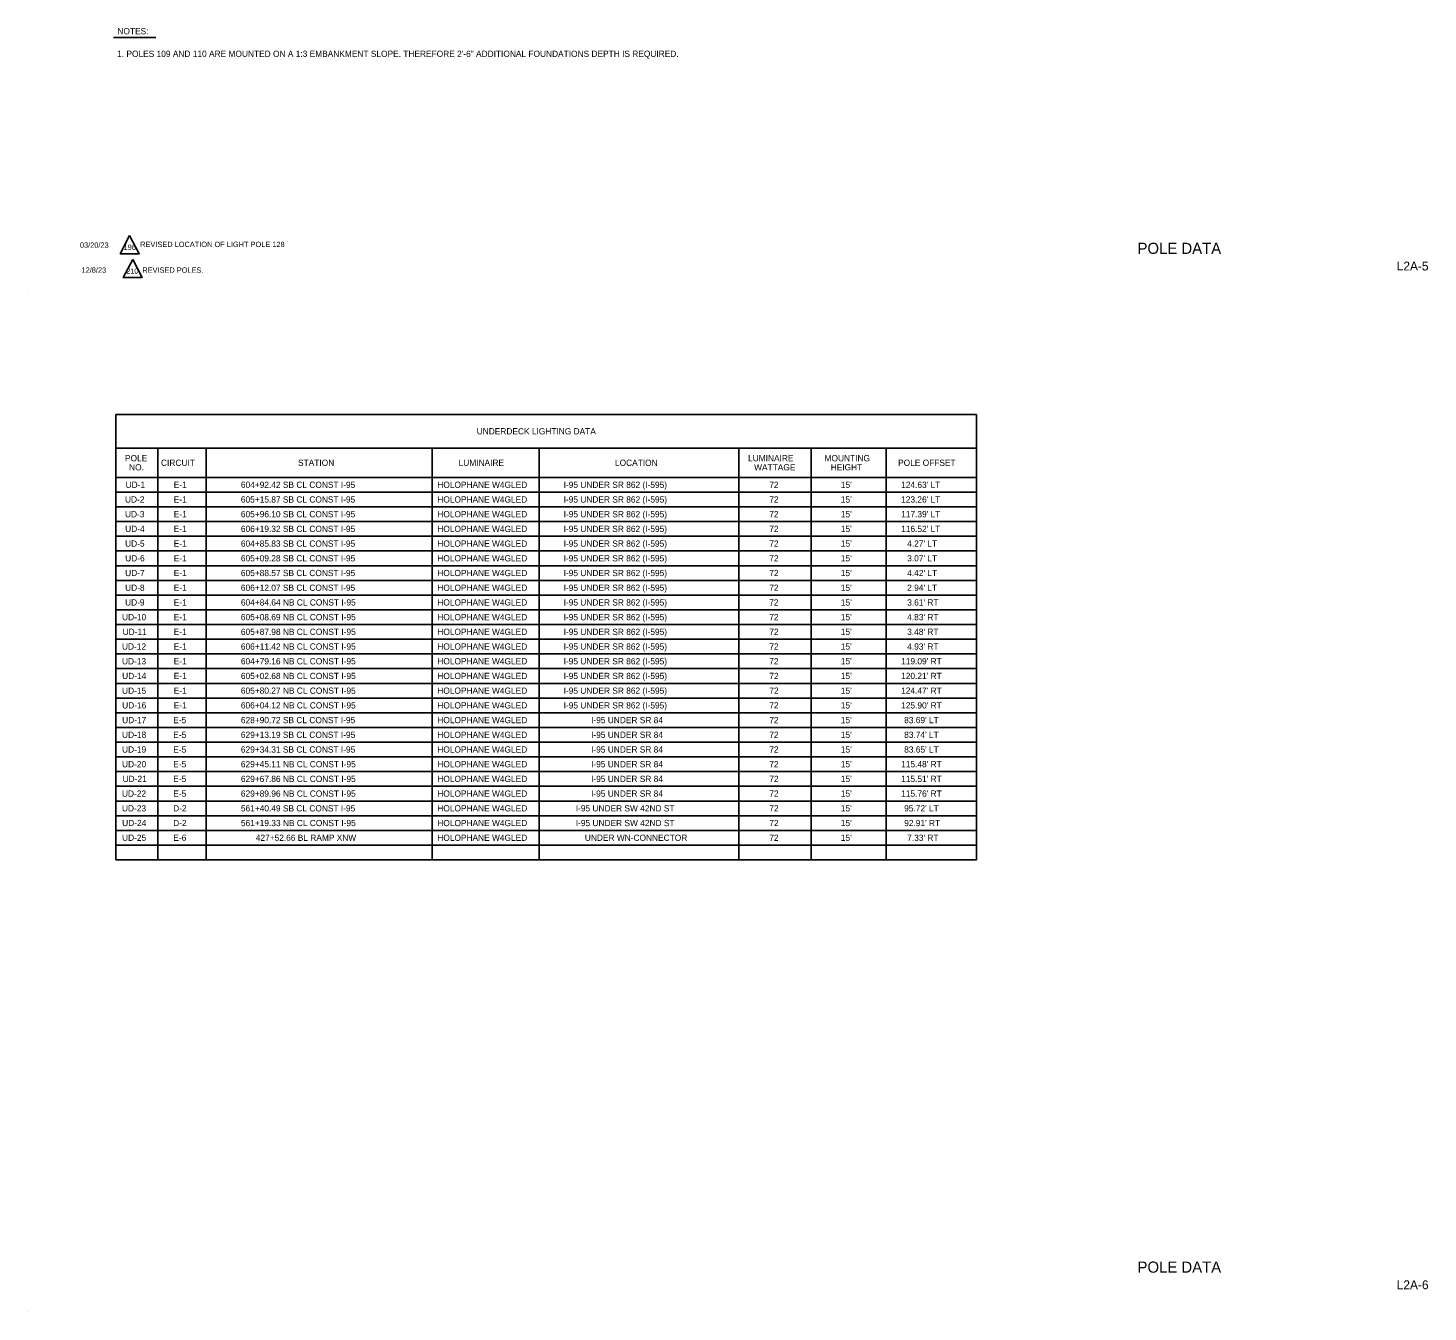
# Model space of a CAD drawing. Extents: x -818.1 to -802.4, y -2221.2 to -2187.7.
# Drawn here: x -818.09 to -802.38, y -2221.15 to -2206.75 of the extents above; entities that cross this region are included whole.
import ezdxf

# ---------------------------------------------------------------- set-up
doc = ezdxf.new("R2010")
doc.units = 0
for name, color, linetype in [('AdhocPoint_dp', 7, 'Continuous'), ('Cloud_dp', 7, 'Continuous'), ('SumBoxBorder_dp', 7, 'Continuous'), ('SumBoxLines_dp', 7, 'Continuous'), ('SumBoxLinesMin_dp', 7, 'Continuous'), ('TextLabel', 7, 'Continuous'), ('TextMisc', 7, 'Continuous'), ('TextShtNo', 7, 'Continuous')]:
    doc.layers.add(name, color=color, linetype=linetype)

msp = doc.modelspace()

# ---------------------------------------------------------------- linework, layer by layer
at = {"layer": 'AdhocPoint_dp'}
for p, q in [((-818.086, -2209.723), (-818.086, -2209.723)), ((-818.086, -2221.153), (-818.086, -2221.153))]:
    msp.add_line(p, q, dxfattribs=at)
at = {"layer": 'Cloud_dp'}
for points in [[(-816.946, -2209.076), (-817.052, -2209.281), (-816.839, -2209.281)], [(-816.911, -2209.344), (-817.017, -2209.547), (-816.806, -2209.547)]]:
    msp.add_lwpolyline(points, close=True, dxfattribs=at)
at = {"layer": 'SumBoxBorder_dp'}
for p, q in [((-817.101, -2211.085), (-807.448, -2211.085)), ((-817.101, -2211.085), (-817.101, -2216.08)), ((-807.448, -2216.08), (-807.448, -2211.085)), ((-817.101, -2211.46), (-807.448, -2211.46)), ((-817.101, -2211.46), (-807.448, -2211.46)), ((-807.448, -2211.79), (-807.448, -2211.955)), ((-807.448, -2212.285), (-807.448, -2212.615)), ((-807.448, -2213.11), (-807.448, -2213.605)), ((-807.448, -2214.43), (-807.448, -2214.595)), ((-807.448, -2215.255), (-807.448, -2215.42)), ((-807.448, -2215.915), (-807.448, -2216.08)), ((-817.101, -2216.08), (-809.301, -2216.08)), ((-809.301, -2216.08), (-808.461, -2216.08)), ((-808.461, -2216.08), (-807.448, -2216.08))]:
    msp.add_line(p, q, dxfattribs=at)
at = {"layer": 'SumBoxLines_dp'}
for p, q in [((-816.628, -2211.46), (-816.628, -2216.08)), ((-816.628, -2211.46), (-816.628, -2216.08)), ((-816.088, -2211.46), (-816.088, -2216.08)), ((-816.088, -2211.46), (-816.088, -2216.08)), ((-813.553, -2211.46), (-813.553, -2212.615)), ((-813.553, -2211.46), (-813.553, -2216.08)), ((-812.353, -2211.46), (-812.353, -2216.08)), ((-812.353, -2211.46), (-812.353, -2216.08)), ((-810.111, -2211.46), (-810.111, -2216.08)), ((-810.111, -2211.46), (-810.111, -2216.08)), ((-809.301, -2211.46), (-809.301, -2216.08)), ((-809.301, -2211.46), (-809.301, -2216.08)), ((-808.461, -2211.46), (-808.461, -2212.285)), ((-808.461, -2211.46), (-808.461, -2216.08)), ((-817.101, -2211.79), (-807.448, -2211.79)), ((-808.461, -2211.79), (-807.448, -2211.79)), ((-808.461, -2212.45), (-808.461, -2213.275)), ((-813.553, -2212.78), (-813.553, -2216.08)), ((-808.461, -2213.44), (-808.461, -2216.08))]:
    msp.add_line(p, q, dxfattribs=at)
at = {"layer": 'SumBoxLinesMin_dp'}
for p, q in [((-817.101, -2211.79), (-808.461, -2211.79)), ((-817.101, -2211.955), (-807.448, -2211.955)), ((-817.101, -2211.955), (-807.448, -2211.955)), ((-817.101, -2212.12), (-807.448, -2212.12)), ((-817.101, -2212.12), (-807.448, -2212.12)), ((-817.101, -2212.285), (-807.448, -2212.285)), ((-817.101, -2212.285), (-807.448, -2212.285)), ((-817.101, -2212.45), (-807.448, -2212.45)), ((-817.101, -2212.45), (-807.448, -2212.45)), ((-817.101, -2212.615), (-807.448, -2212.615)), ((-817.101, -2212.615), (-807.448, -2212.615)), ((-817.101, -2212.78), (-816.088, -2212.78)), ((-817.101, -2212.78), (-807.448, -2212.78)), ((-813.553, -2212.78), (-807.448, -2212.78)), ((-817.101, -2212.945), (-807.448, -2212.945)), ((-817.101, -2212.945), (-807.448, -2212.945)), ((-817.101, -2213.11), (-807.448, -2213.11)), ((-817.101, -2213.11), (-807.448, -2213.11)), ((-817.101, -2213.275), (-807.448, -2213.275)), ((-817.101, -2213.275), (-807.448, -2213.275)), ((-817.101, -2213.44), (-807.448, -2213.44)), ((-817.101, -2213.44), (-807.448, -2213.44)), ((-817.101, -2213.605), (-807.448, -2213.605)), ((-817.101, -2213.605), (-807.448, -2213.605)), ((-817.101, -2213.77), (-807.448, -2213.77)), ((-817.101, -2213.77), (-807.448, -2213.77)), ((-817.101, -2213.935), (-807.448, -2213.935)), ((-817.101, -2213.935), (-807.448, -2213.935)), ((-817.101, -2214.1), (-807.448, -2214.1)), ((-817.101, -2214.1), (-807.448, -2214.1)), ((-817.101, -2214.265), (-807.448, -2214.265)), ((-817.101, -2214.265), (-807.448, -2214.265)), ((-817.101, -2214.43), (-807.448, -2214.43)), ((-817.101, -2214.43), (-807.448, -2214.43)), ((-817.101, -2214.595), (-807.448, -2214.595)), ((-817.101, -2214.595), (-807.448, -2214.595)), ((-817.101, -2214.76), (-807.448, -2214.76)), ((-817.101, -2214.76), (-807.448, -2214.76)), ((-817.101, -2214.925), (-807.448, -2214.925)), ((-817.101, -2214.925), (-807.448, -2214.925)), ((-817.101, -2215.09), (-807.448, -2215.09)), ((-817.101, -2215.09), (-807.448, -2215.09)), ((-817.101, -2215.255), (-807.448, -2215.255)), ((-817.101, -2215.255), (-807.448, -2215.255)), ((-817.101, -2215.42), (-807.448, -2215.42)), ((-817.101, -2215.42), (-807.448, -2215.42)), ((-817.101, -2215.585), (-816.628, -2215.585)), ((-817.101, -2215.585), (-807.448, -2215.585)), ((-813.553, -2215.585), (-812.353, -2215.585)), ((-817.101, -2215.75), (-816.628, -2215.75)), ((-817.101, -2215.75), (-807.448, -2215.75)), ((-813.553, -2215.75), (-812.353, -2215.75)), ((-817.101, -2215.915), (-807.448, -2215.915)), ((-813.553, -2215.915), (-812.353, -2215.915))]:
    msp.add_line(p, q, dxfattribs=at)
at = {"layer": 'TextLabel'}
msp.add_line((-817.128, -2206.854), (-816.652, -2206.854), dxfattribs=at)

# ---------------------------------------------------------------- texts
at = {"layer": 'Cloud_dp'}
for s, height, p in [('03/20/23', 0.06, (-817.504, -2209.213)), ('196', 0.06, (-817.014, -2209.238)), ('REVISED LOCATION OF LIGHT POLE 128', 0.06, (-816.828, -2209.205)), ('12/8/23', 0.06, (-817.486, -2209.494)), ('210', 0.057, (-816.982, -2209.503)), ('REVISED POLES.', 0.06, (-816.804, -2209.494))]:
    msp.add_text(s, height=height, dxfattribs=at).set_placement(p)
at = {"layer": 'TextLabel'}
for s, p in [('NOTES:', (-817.083, -2206.818)), ('1. POLES 109 AND 110 ARE MOUNTED ON A 1:3 EMBANKMENT SLOPE. THEREFORE 2\'-6" ADDITIONAL FOUNDATIONS DEPTH IS REQUIRED.', (-817.086, -2207.072)), ('UNDERDECK LIGHTING DATA', (-813.053, -2211.307)), ('POLE', (-816.998, -2211.609)), ('CIRCUIT', (-816.594, -2211.66)), ('STATION', (-815.057, -2211.66)), ('LUMINAIRE', (-813.256, -2211.66)), ('LOCATION', (-811.502, -2211.66)), ('LUMINAIRE', (-810.009, -2211.609)), ('MOUNTING', (-809.151, -2211.609)), ('POLE OFFSET', (-808.326, -2211.66)), ('NO.', (-816.952, -2211.711)), ('WATTAGE', (-809.941, -2211.711)), ('HEIGHT', (-809.082, -2211.711)), ('UD-1', (-816.991, -2211.907)), ('E-1', (-816.451, -2211.907)), ('604+92.42 SB CL CONST I-95', (-815.698, -2211.907)), ('HOLOPHANE W4GLED', (-813.495, -2211.907)), (' I-95 UNDER SR 862 (I-595)', (-812.104, -2211.907)), ('72', (-809.771, -2211.907)), ("15'", (-808.969, -2211.907)), ("124.63' LT", (-808.292, -2211.907)), ('UD-2', (-816.998, -2212.072)), ('E-1', (-816.451, -2212.072)), ('605+15.87 SB CL CONST I-95', (-815.698, -2212.072)), ('HOLOPHANE W4GLED', (-813.495, -2212.072)), (' I-95 UNDER SR 862 (I-595)', (-812.104, -2212.072)), ('72', (-809.771, -2212.072)), ("15'", (-808.969, -2212.072)), ("123.26' LT", (-808.292, -2212.072)), ('UD-3', (-816.998, -2212.237)), ('E-1', (-816.451, -2212.237)), ('605+96.10 SB CL CONST I-95', (-815.698, -2212.237)), ('HOLOPHANE W4GLED', (-813.495, -2212.237)), (' I-95 UNDER SR 862 (I-595)', (-812.104, -2212.237)), ('72', (-809.771, -2212.237)), ("15'", (-808.969, -2212.237)), ("117.39' LT", (-808.292, -2212.237)), ('UD-4', (-816.996, -2212.402)), ('E-1', (-816.451, -2212.402)), ('606+19.32 SB CL CONST I-95', (-815.698, -2212.402)), ('HOLOPHANE W4GLED', (-813.495, -2212.402)), (' I-95 UNDER SR 862 (I-595)', (-812.104, -2212.402)), ('72', (-809.771, -2212.402)), ("15'", (-808.969, -2212.402)), ("116.52' LT", (-808.292, -2212.402)), ('UD-5', (-816.997, -2212.567)), ('E-1', (-816.451, -2212.567)), ('604+85.83 SB CL CONST I-95', (-815.698, -2212.567)), ('HOLOPHANE W4GLED', (-813.495, -2212.567)), (' I-95 UNDER SR 862 (I-595)', (-812.104, -2212.567)), ('72', (-809.771, -2212.567)), ("15'", (-808.969, -2212.567)), ("4.27' LT", (-808.224, -2212.567)), ('UD-6', (-816.996, -2212.732)), ('E-1', (-816.451, -2212.732)), ('605+09.28 SB CL CONST I-95', (-815.698, -2212.732)), ('HOLOPHANE W4GLED', (-813.495, -2212.732)), (' I-95 UNDER SR 862 (I-595)', (-812.104, -2212.732)), ('72', (-809.771, -2212.732)), ("15'", (-808.969, -2212.732)), ("3.07' LT", (-808.224, -2212.732)), ('UD-7', (-816.996, -2212.897)), ('E-1', (-816.451, -2212.897)), ('605+88.57 SB CL CONST I-95', (-815.698, -2212.897)), ('HOLOPHANE W4GLED', (-813.495, -2212.897)), (' I-95 UNDER SR 862 (I-595)', (-812.104, -2212.897)), ('72', (-809.771, -2212.897)), ("15'", (-808.969, -2212.897)), ("4.42' LT", (-808.224, -2212.897)), ('UD-8', (-816.997, -2213.062)), ('E-1', (-816.451, -2213.062)), ('606+12.07 SB CL CONST I-95', (-815.698, -2213.062)), ('HOLOPHANE W4GLED', (-813.495, -2213.062)), (' I-95 UNDER SR 862 (I-595)', (-812.104, -2213.062)), ('72', (-809.771, -2213.062)), ("15'", (-808.969, -2213.062)), ("2.94' LT", (-808.224, -2213.062)), ('UD-9', (-816.997, -2213.227)), ('E-1', (-816.451, -2213.227)), ('604+84.64 NB CL CONST I-95', (-815.698, -2213.227)), ('HOLOPHANE W4GLED', (-813.495, -2213.227)), (' I-95 UNDER SR 862 (I-595)', (-812.104, -2213.227)), ('72', (-809.771, -2213.227)), ("15'", (-808.969, -2213.227)), ("3.61' RT", (-808.224, -2213.227)), ('UD-10', (-817.031, -2213.392)), ('E-1', (-816.451, -2213.392)), ('605+08.69 NB CL CONST I-95', (-815.698, -2213.392)), ('HOLOPHANE W4GLED', (-813.495, -2213.392)), (' I-95 UNDER SR 862 (I-595)', (-812.104, -2213.392)), ('72', (-809.771, -2213.392)), ("15'", (-808.969, -2213.392)), ("4.83' RT", (-808.224, -2213.392)), ('UD-11', (-817.025, -2213.557)), ('E-1', (-816.451, -2213.557)), ('605+87.98 NB CL CONST I-95', (-815.698, -2213.557)), ('HOLOPHANE W4GLED', (-813.495, -2213.557)), (' I-95 UNDER SR 862 (I-595)', (-812.104, -2213.557)), ('72', (-809.771, -2213.557)), ("15'", (-808.969, -2213.557)), ("3.48' RT", (-808.224, -2213.557)), ('UD-12', (-817.032, -2213.722)), ('E-1', (-816.451, -2213.722)), ('606+11.42 NB CL CONST I-95', (-815.698, -2213.722)), ('HOLOPHANE W4GLED', (-813.495, -2213.722)), (' I-95 UNDER SR 862 (I-595)', (-812.104, -2213.722)), ('72', (-809.771, -2213.722)), ("15'", (-808.969, -2213.722)), ("4.93' RT", (-808.224, -2213.722)), ('UD-13', (-817.032, -2213.887)), ('E-1', (-816.451, -2213.887)), ('604+79.16 NB CL CONST I-95', (-815.698, -2213.887)), ('HOLOPHANE W4GLED', (-813.495, -2213.887)), (' I-95 UNDER SR 862 (I-595)', (-812.104, -2213.887)), ('72', (-809.771, -2213.887)), ("15'", (-808.969, -2213.887)), ("119.09' RT", (-808.292, -2213.887)), ('UD-14', (-817.03, -2214.052)), ('E-1', (-816.451, -2214.052)), ('605+02.68 NB CL CONST I-95', (-815.698, -2214.052)), ('HOLOPHANE W4GLED', (-813.495, -2214.052)), (' I-95 UNDER SR 862 (I-595)', (-812.104, -2214.052)), ('72', (-809.771, -2214.052)), ("15'", (-808.969, -2214.052)), ("120.21' RT", (-808.292, -2214.052)), ('UD-15', (-817.031, -2214.217)), ('E-1', (-816.451, -2214.217)), ('605+80.27 NB CL CONST I-95', (-815.698, -2214.217)), ('HOLOPHANE W4GLED', (-813.495, -2214.217)), (' I-95 UNDER SR 862 (I-595)', (-812.104, -2214.217)), ('72', (-809.771, -2214.217)), ("15'", (-808.969, -2214.217)), ("124.47' RT", (-808.292, -2214.217)), ('UD-16', (-817.03, -2214.382)), ('E-1', (-816.451, -2214.382)), ('606+04.12 NB CL CONST I-95', (-815.698, -2214.382)), ('HOLOPHANE W4GLED', (-813.495, -2214.382)), (' I-95 UNDER SR 862 (I-595)', (-812.104, -2214.382)), ('72', (-809.771, -2214.382)), ("15'", (-808.969, -2214.382)), ("125.90' RT", (-808.292, -2214.382)), ('UD-17', (-817.03, -2214.547)), ('E-5', (-816.457, -2214.547)), ('628+90.72 SB CL CONST I-95', (-815.698, -2214.547)), ('HOLOPHANE W4GLED', (-813.495, -2214.547)), ('I-95 UNDER SR 84', (-811.77, -2214.547)), ('72', (-809.771, -2214.547)), ("15'", (-808.969, -2214.547)), ("83.69' LT", (-808.258, -2214.547)), ('UD-18', (-817.031, -2214.712)), ('E-5', (-816.457, -2214.712)), ('629+13.19 SB CL CONST I-95', (-815.698, -2214.712)), ('HOLOPHANE W4GLED', (-813.495, -2214.712)), ('I-95 UNDER SR 84', (-811.77, -2214.712)), ('72', (-809.771, -2214.712)), ("15'", (-808.969, -2214.712)), ("83.74' LT", (-808.258, -2214.712)), ('UD-19', (-817.031, -2214.877)), ('E-5', (-816.457, -2214.877)), ('629+34.31 SB CL CONST I-95', (-815.698, -2214.877)), ('HOLOPHANE W4GLED', (-813.495, -2214.877)), ('I-95 UNDER SR 84', (-811.77, -2214.877)), ('72', (-809.771, -2214.877)), ("15'", (-808.969, -2214.877)), ("83.65' LT", (-808.258, -2214.877)), ('UD-20', (-817.031, -2215.042)), ('E-5', (-816.457, -2215.042)), ('629+45.11 NB CL CONST I-95', (-815.698, -2215.042)), ('HOLOPHANE W4GLED', (-813.495, -2215.042)), ('I-95 UNDER SR 84', (-811.77, -2215.042)), ('72', (-809.771, -2215.042)), ("15'", (-808.969, -2215.042)), ("115.48' RT", (-808.292, -2215.042)), ('UD-21', (-817.025, -2215.207)), ('E-5', (-816.457, -2215.207)), ('629+67.86 NB CL CONST I-95', (-815.698, -2215.207)), ('HOLOPHANE W4GLED', (-813.495, -2215.207)), ('I-95 UNDER SR 84', (-811.77, -2215.207)), ('72', (-809.771, -2215.207)), ("15'", (-808.969, -2215.207)), ("115.51' RT", (-808.292, -2215.207)), ('UD-22', (-817.032, -2215.372)), ('E-5', (-816.457, -2215.372)), ('629+89.96 NB CL CONST I-95', (-815.698, -2215.372)), ('HOLOPHANE W4GLED', (-813.495, -2215.372)), ('I-95 UNDER SR 84', (-811.77, -2215.372)), ('72', (-809.771, -2215.372)), ("15'", (-808.969, -2215.372)), ("115.76' RT", (-808.292, -2215.372)), ('UD-23', (-817.032, -2215.537)), ('D-2', (-816.458, -2215.537)), ('561+40.49 SB CL CONST I-95', (-815.698, -2215.537)), ('HOLOPHANE W4GLED', (-813.495, -2215.537)), ('I-95 UNDER SW 42ND ST', (-811.942, -2215.537)), ('72', (-809.771, -2215.537)), ("15'", (-808.969, -2215.537)), ("95.72' LT", (-808.258, -2215.537)), ('UD-24', (-817.03, -2215.702)), ('D-2', (-816.458, -2215.702)), ('561+19.33 NB CL CONST I-95', (-815.698, -2215.702)), ('HOLOPHANE W4GLED', (-813.495, -2215.702)), ('I-95 UNDER SW 42ND ST', (-811.942, -2215.702)), ('72', (-809.771, -2215.702)), ("15'", (-808.969, -2215.702)), ("92.91' RT", (-808.258, -2215.702)), ('UD-25', (-817.031, -2215.867)), ('E-6', (-816.456, -2215.867)), ('427+52.66 BL RAMP XNW', (-815.531, -2215.867)), ('HOLOPHANE W4GLED', (-813.495, -2215.867)), ('UNDER WN-CONNECTOR', (-811.84, -2215.867)), ('72', (-809.771, -2215.867)), ("15'", (-808.969, -2215.867)), ("7.33' RT", (-808.224, -2215.867))]:
    msp.add_text(s, height=0.07, dxfattribs=at).set_placement(p)
at = {"layer": 'TextMisc'}
for p in [(-806.105, -2209.282), (-806.105, -2220.712)]:
    msp.add_text('          POLE DATA            ', height=0.125, dxfattribs=at).set_placement(p)
at = {"layer": 'TextShtNo'}
for s, p in [('L2A-5 ', (-802.733, -2209.468)), ('L2A-6 ', (-802.733, -2220.898))]:
    msp.add_text(s, height=0.1, dxfattribs=at).set_placement(p)

doc.saveas('drawing.dxf')
